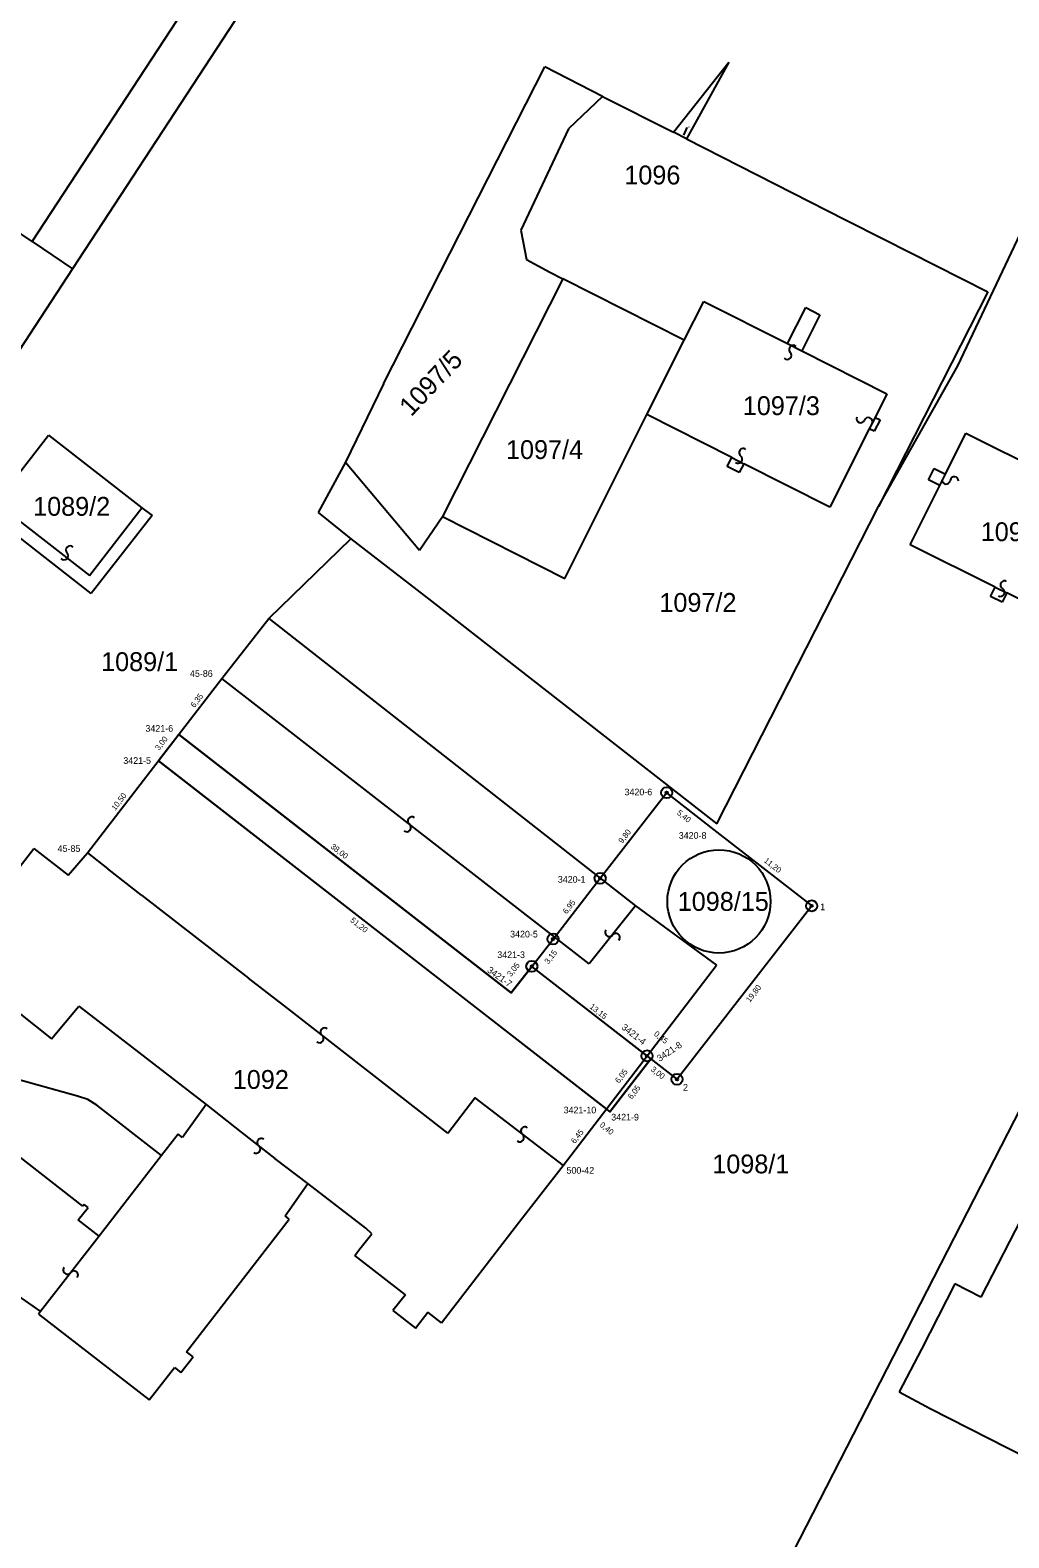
# Model space of a CAD drawing. Extents: x -621172 to -616925, y -1123899 to -1119548.
# Drawn here: x -619154.3 to -619066, y -1121541.1 to -1121405.1 of the extents above; entities that cross this region are included whole.
import ezdxf

# ---------------------------------------------------------------- set-up
doc = ezdxf.new("R2010")
doc.units = 0
for name, color, linetype in [('Vrstva 1', 7, 'Continuous'), ('Vrstva 16', 7, 'Continuous'), ('Vrstva 18', 7, 'Continuous'), ('Vrstva 19', 7, 'Continuous'), ('Vrstva 24', 7, 'Continuous'), ('Vrstva 25', 7, 'Continuous'), ('Vrstva 4', 7, 'Continuous'), ('Vrstva 58', 7, 'Continuous'), ('Vrstva 60', 7, 'Continuous')]:
    doc.layers.add(name, color=color, linetype=linetype)

msp = doc.modelspace()

# ---------------------------------------------------------------- linework, layer by layer
at = {"layer": 'Vrstva 1'}
for points in [[(-619154.13, -1121424.18), (-619231.87, -1121371.5)], [(-619154.13, -1121424.18), (-619131.38, -1121389.44)], [(-619126.66, -1121390.22), (-619150.5, -1121426.64)], [(-619070.6, -1121435.39), (-619056.33, -1121405.28)], [(-619122.41, -1121437.01), (-619107.86, -1121408.43)], [(-619102.66, -1121411.09), (-619107.86, -1121408.43)], [(-619096.26, -1121414.32), (-619091.26, -1121408.01)], [(-619091.26, -1121408.01), (-619095.07, -1121414.92)], [(-619102.66, -1121411.09), (-619105.72, -1121414.02)], [(-619102.66, -1121411.09), (-619096.26, -1121414.32)], [(-619105.72, -1121414.02), (-619110.04, -1121423.16)], [(-619095.07, -1121414.92), (-619096.26, -1121414.32)], [(-619095.07, -1121414.92), (-619080.74, -1121422.22)], [(-619080.74, -1121422.22), (-619077.26, -1121423.98)], [(-619154.13, -1121424.18), (-619150.5, -1121426.64)], [(-619110.04, -1121423.16), (-619109.52, -1121425.79)], [(-619077.26, -1121423.98), (-619067.88, -1121428.73)], [(-619150.5, -1121426.64), (-619163.54, -1121446.57)], [(-619109.52, -1121425.79), (-619107.42, -1121426.94)], [(-619107.42, -1121426.94), (-619106.24, -1121427.54)], [(-619106.24, -1121427.54), (-619117.1, -1121449)], [(-619095.28, -1121433.09), (-619106.24, -1121427.54)], [(-619095.28, -1121433.09), (-619093.5, -1121429.58)], [(-619093.5, -1121429.58), (-619085.97, -1121433.39)], [(-619067.88, -1121428.73), (-619077.75, -1121448.09)], [(-619085.97, -1121433.39), (-619084.32, -1121430.12)], [(-619083.03, -1121430.78), (-619084.68, -1121434.04)], [(-619084.32, -1121430.12), (-619083.03, -1121430.78)], [(-619098.66, -1121439.79), (-619095.28, -1121433.09)], [(-619084.68, -1121434.04), (-619076.99, -1121437.93)], [(-619077.75, -1121448.09), (-619070.6, -1121435.39)], [(-619122.41, -1121437.01), (-619125.86, -1121444.07)], [(-619076.99, -1121437.93), (-619078.06, -1121440.04)], [(-619106.06, -1121454.59), (-619098.66, -1121439.79)], [(-619090.99, -1121443.67), (-619098.66, -1121439.79)], [(-619077.61, -1121440.27), (-619078.13, -1121441.29)], [(-619078.06, -1121440.04), (-619077.61, -1121440.27)], [(-619157.41, -1121447.76), (-619152.66, -1121441.64)], [(-619152.66, -1121441.64), (-619144.22, -1121448.19)], [(-619078.58, -1121441.07), (-619082.15, -1121448.14)], [(-619078.13, -1121441.29), (-619078.58, -1121441.07)], [(-619071.71, -1121445.16), (-619069.87, -1121441.47)], [(-619069.87, -1121441.47), (-619062.56, -1121445.12)], [(-619125.86, -1121444.07), (-619128.32, -1121448.62)], [(-619125.86, -1121444.07), (-619119.18, -1121452.03)], [(-619091.4, -1121444.47), (-619090.99, -1121443.67)], [(-619090.31, -1121445.02), (-619091.4, -1121444.47)], [(-619089.9, -1121444.22), (-619090.31, -1121445.02)], [(-619082.15, -1121448.14), (-619089.9, -1121444.22)], [(-619073.24, -1121445.68), (-619072.73, -1121444.65)], [(-619072.22, -1121446.19), (-619073.24, -1121445.68)], [(-619072.73, -1121444.65), (-619071.71, -1121445.16)], [(-619074.88, -1121451.54), (-619072.22, -1121446.19)], [(-619148.81, -1121455.94), (-619158.11, -1121448.67)], [(-619144.22, -1121448.19), (-619143.3, -1121448.91)], [(-619128.32, -1121448.62), (-619125.37, -1121451)], [(-619092.34, -1121476.71), (-619077.75, -1121448.09)], [(-619143.3, -1121448.91), (-619148.81, -1121455.94)], [(-619119.18, -1121452.03), (-619117.1, -1121449)], [(-619117.1, -1121449), (-619106.06, -1121454.59)], [(-619132.76, -1121458.2), (-619125.37, -1121451)], [(-619125.37, -1121451), (-619118.1, -1121456.61)], [(-619067.21, -1121455.36), (-619074.88, -1121451.54)], [(-619067.63, -1121456.2), (-619067.21, -1121455.36)], [(-619118.1, -1121456.61), (-619092.34, -1121476.71)], [(-619066.58, -1121456.72), (-619067.63, -1121456.2)], [(-619066.16, -1121455.88), (-619066.58, -1121456.72)], [(-619058.52, -1121459.68), (-619066.16, -1121455.88)], [(-619137.02, -1121463.61), (-619132.76, -1121458.2)], [(-619132.76, -1121458.2), (-619102.87, -1121481.62)], [(-619149.15, -1121479.34), (-619137.02, -1121463.61)], [(-619140.9, -1121468.65), (-619110.9, -1121491.96), (-619109.04, -1121489.57)], [(-619102.31, -1121502.43), (-619142.74, -1121471.02)], [(-619102.87, -1121481.62), (-619096.87, -1121473.9)], [(-619096.87, -1121473.9), (-619092.61, -1121477.25)], [(-619092.61, -1121477.25), (-619083.78, -1121484.11)], [(-619161.05, -1121488.05), (-619153.98, -1121478.94)], [(-619153.98, -1121478.94), (-619150.88, -1121481.34)], [(-619150.88, -1121481.34), (-619149.15, -1121479.34)], [(-619107.12, -1121487.1), (-619102.87, -1121481.62)], [(-619102.87, -1121481.62), (-619099.68, -1121484.12)], [(-619099.68, -1121484.12), (-619092.36, -1121489.45)], [(-619083.78, -1121484.11), (-619095.93, -1121499.75)], [(-619109.04, -1121489.57), (-619107.12, -1121487.1)], [(-619161.26, -1121489.06), (-619152.38, -1121496.1)], [(-619098.64, -1121497.64), (-619092.36, -1121489.45)], [(-619098.64, -1121497.64), (-619109.04, -1121489.57)], [(-619152.38, -1121496.1), (-619149.92, -1121493.15)], [(-619149.92, -1121493.15), (-619138.43, -1121502.02)], [(-619150.05, -1121501.29), (-619164.96, -1121497.14)], [(-619106.22, -1121507.53), (-619098.64, -1121497.64)], [(-619095.93, -1121499.75), (-619098.64, -1121497.64)], [(-619098.29, -1121497.91), (-619102, -1121502.68), (-619102.31, -1121502.43)], [(-619149.56, -1121511.19), (-619164.31, -1121499.7)], [(-619149.12, -1121501.57), (-619150.05, -1121501.29)], [(-619148.31, -1121502.09), (-619149.12, -1121501.57)], [(-619142.46, -1121506.63), (-619148.31, -1121502.09)], [(-619138.43, -1121502.02), (-619140.56, -1121505)], [(-619064.91, -1121502.3), (-619094.57, -1121560.13)], [(-619140.96, -1121504.7), (-619142.46, -1121506.63)], [(-619140.56, -1121505), (-619140.96, -1121504.7)], [(-619142.46, -1121506.63), (-619148.1, -1121513.9)], [(-619110.23, -1121512.71), (-619106.22, -1121507.53)], [(-619131.3, -1121512.06), (-619129.25, -1121509.14)], [(-619124.01, -1121513.17), (-619129.25, -1121509.14)], [(-619149.44, -1121511.04), (-619149.56, -1121511.19)], [(-619149.09, -1121511.33), (-619149.44, -1121511.04)], [(-619149.97, -1121512.44), (-619149.09, -1121511.33)], [(-619148.1, -1121513.9), (-619149.97, -1121512.44)], [(-619140.19, -1121524.33), (-619130.94, -1121512.38)], [(-619130.94, -1121512.38), (-619131.3, -1121512.06)], [(-619064.4, -1121511.4), (-619068.52, -1121519.41)], [(-619124.57, -1121515.05), (-619123.47, -1121513.69)], [(-619123.47, -1121513.69), (-619124.01, -1121513.17)], [(-619117.2, -1121521.71), (-619110.23, -1121512.71)], [(-619125, -1121515.66), (-619124.57, -1121515.05)], [(-619120.45, -1121519.19), (-619125, -1121515.66)], [(-619155.46, -1121519.27), (-619153.38, -1121520.7)], [(-619120.45, -1121519.19), (-619121.57, -1121520.6)], [(-619070.85, -1121518.21), (-619073.88, -1121524.1)], [(-619068.52, -1121519.41), (-619070.85, -1121518.21)], [(-619153.38, -1121520.7), (-619153.56, -1121520.93)], [(-619121.57, -1121520.6), (-619119.55, -1121522.19)], [(-619119.55, -1121522.19), (-619118.43, -1121520.76)], [(-619117.2, -1121521.71), (-619118.43, -1121520.76)], [(-619153.56, -1121520.93), (-619143.57, -1121528.68)], [(-619140.7, -1121526.2), (-619139.6, -1121524.79)], [(-619139.6, -1121524.79), (-619140.19, -1121524.33)], [(-619073.88, -1121524.1), (-619075.89, -1121527.96)], [(-619143.57, -1121528.68), (-619141.29, -1121525.74)], [(-619141.29, -1121525.74), (-619140.7, -1121526.2)], [(-619075.89, -1121527.96), (-619073.1, -1121529.44)], [(-619073.1, -1121529.44), (-619062.57, -1121534.81)]]:
    msp.add_lwpolyline(points, dxfattribs=at)
msp.add_lwpolyline([(-619102, -1121502.68), (-619098.29, -1121497.91), (-619109.04, -1121489.57), (-619110.9, -1121491.96), (-619140.9, -1121468.65), (-619142.74, -1121471.02)], close=True, dxfattribs=at)
at = {"layer": 'Vrstva 16'}
msp.add_line((-619095.04, -1121413.9), (-619095.355, -1121414.596), dxfattribs=at)
at = {"layer": 'Vrstva 18'}
msp.add_circle((-619092.15, -1121483.71), 4.656, dxfattribs=at)
at = {"layer": 'Vrstva 24'}
for centre, radius in [((-619096.87, -1121473.9), 0.5), ((-619096.87, -1121473.9), 0.1), ((-619102.87, -1121481.62), 0.5), ((-619102.87, -1121481.62), 0.1), ((-619083.78, -1121484.11), 0.5), ((-619083.78, -1121484.11), 0.1), ((-619107.12, -1121487.1), 0.5), ((-619107.12, -1121487.1), 0.1), ((-619109.04, -1121489.57), 0.5), ((-619109.04, -1121489.57), 0.1), ((-619098.64, -1121497.64), 0.5), ((-619098.64, -1121497.64), 0.1), ((-619095.93, -1121499.75), 0.5), ((-619095.93, -1121499.75), 0.1)]:
    msp.add_circle(centre, radius, dxfattribs=at)
at = {"layer": 'Vrstva 25'}
for centre, start, end in [((-619085.451, -1121433.918), 44.22538, 224.22538), ((-619085.989, -1121434.442), 224.22538, 44.22537), ((-619079.368, -1121440.16), 158.09026, 338.09026), ((-619078.672, -1121440.44), 338.09026, 158.09026), ((-619089.96, -1121443.223), 52.25716, 232.25716), ((-619090.42, -1121443.817), 232.25716, 52.25716), ((-619071.653, -1121445.69), 173.81811, 353.81811), ((-619070.907, -1121445.77), 353.81811, 173.81811), ((-619151.263, -1121452.528), 223.3699, 43.3699), ((-619150.717, -1121452.012), 43.3699, 223.3699), ((-619066.744, -1121455.817), 240.58114, 60.58114), ((-619066.376, -1121455.163), 60.58114, 240.58114), ((-619120.319, -1121477.047), 232.29046, 52.29046), ((-619119.861, -1121476.453), 52.29046, 232.29046), ((-619102.053, -1121486.496), 141.37186, 321.37186), ((-619101.467, -1121486.964), 321.37186, 141.37186), ((-619128.2, -1121496.086), 232.15921, 52.15921), ((-619127.74, -1121495.494), 52.15921, 232.15921), ((-619109.662, -1121504.422), 52.62888, 232.62888), ((-619133.91, -1121506.057), 232.26452, 52.26452), ((-619133.45, -1121505.463), 52.26452, 232.26452), ((-619110.118, -1121505.018), 232.62888, 52.62888), ((-619150.957, -1121516.961), 142.39674, 322.39674), ((-619150.363, -1121517.419), 322.39674, 142.39674)]:
    msp.add_arc(centre, 0.375, start, end, dxfattribs=at)
at = {"layer": 'Vrstva 4'}
for points in [[(-619085.97, -1121433.39), (-619084.68, -1121434.04)], [(-619078.06, -1121440.04), (-619078.58, -1121441.07)], [(-619090.99, -1121443.67), (-619089.9, -1121444.22)], [(-619072.22, -1121446.19), (-619071.71, -1121445.16)], [(-619157.41, -1121447.76), (-619148.96, -1121454.32)], [(-619148.96, -1121454.32), (-619144.22, -1121448.19)], [(-619067.21, -1121455.36), (-619066.16, -1121455.88)], [(-619103.85, -1121489.35), (-619137.02, -1121463.61)], [(-619149.15, -1121479.34), (-619147.3, -1121480.78)], [(-619144.27, -1121483.13), (-619147.3, -1121480.78)], [(-619144.27, -1121483.13), (-619134.61, -1121490.63)], [(-619099.68, -1121484.12), (-619103.85, -1121489.35)], [(-619131.07, -1121493.38), (-619134.61, -1121490.63)], [(-619116.62, -1121504.61), (-619131.07, -1121493.38)], [(-619116.62, -1121504.61), (-619114.18, -1121501.43), (-619106.22, -1121507.53)], [(-619138.43, -1121502.02), (-619135.28, -1121504.52)], [(-619135.28, -1121504.52), (-619132.22, -1121506.89)], [(-619129.25, -1121509.14), (-619132.22, -1121506.89)], [(-619148.1, -1121513.9), (-619153.38, -1121520.7)]]:
    msp.add_lwpolyline(points, dxfattribs=at)

# ---------------------------------------------------------------- texts
at = {"layer": 'Vrstva 16'}
msp.add_text('1096', height=1.7, dxfattribs=at).set_placement((-619100.688, -1121419.03))
at = {"layer": 'Vrstva 18'}
for s, height, p in [('1096', 0.1, (-619095.04, -1121413.9)), ('1097/2', 1.7, (-619097.523, -1121457.59)), ('1089/1', 1.7, (-619147.91, -1121462.93)), ('1098/15', 1.7, (-619095.87, -1121484.56)), ('1098/1', 1.7, (-619092.75, -1121508.24))]:
    msp.add_text(s, height=height, dxfattribs=at).set_placement(p)
msp.add_text('1097/5', height=1.7, rotation=46.8, dxfattribs=at).set_placement((-619119.92, -1121440.041))
at = {"layer": 'Vrstva 19'}
for s, p in [('1097/3', (-619089.995, -1121439.84)), ('1097/4', (-619111.368, -1121443.8)), ('1089/2', (-619154.043, -1121448.92)), ('1098/10', (-619068.522, -1121451.21)), ('1092', (-619136.024, -1121500.62))]:
    msp.add_text(s, height=1.7, dxfattribs=at).set_placement(p)
at = {"layer": 'Vrstva 58'}
for s, rotation, p in [('6,35', 52.40944, (-619139.479, -1121466.28)), ('3,00', 52.17526, (-619142.685, -1121470.134)), ('10,50', 52.38817, (-619146.636, -1121475.553)), ('5,40', 321.81902, (-619095.996, -1121475.808)), ('9,80', 52.14558, (-619100.868, -1121478.522)), ('38,00', 322.15279, (-619127.248, -1121478.853)), ('11,20', 322.15648, (-619088.138, -1121480.116)), ('6,95', 52.20473, (-619105.887, -1121484.89)), ('51,20', 322.15643, (-619125.466, -1121485.504)), ('3,15', 52.14108, (-619107.541, -1121489.402)), ('3,05', 52.10842, (-619110.915, -1121490.546)), ('19,80', 52.158, (-619089.359, -1121492.857)), ('13,15', 322.18991, (-619103.87, -1121493.303)), ('0,45', 322.35238, (-619098.065, -1121495.76)), ('6,05', 52.5414, (-619101.169, -1121500.152)), ('3,00', 322.05785, (-619098.35, -1121498.953)), ('6,05', 52.12502, (-619100.017, -1121501.597)), ('6,45', 52.52382, (-619105.145, -1121505.602)), ('0,40', 321.1155, (-619102.961, -1121503.96))]:
    msp.add_text(s, height=0.52, rotation=rotation, dxfattribs=at).set_placement(p)
at = {"layer": 'Vrstva 60'}
for s, p in [('45-86', (-619139.89, -1121463.45)), ('3421-6', (-619143.909, -1121468.4)), ('3421-5', (-619145.906, -1121471.3)), ('3420-6', (-619100.67, -1121474.14)), ('45-85', (-619151.837, -1121479.24)), ('3420-8', (-619095.777, -1121478.06)), ('3420-1', (-619106.691, -1121482.02)), ('1', (-619083.01, -1121484.5)), ('3420-5', (-619110.997, -1121486.96)), ('3421-3', (-619112.156, -1121488.82)), ('2', (-619095.39, -1121500.78)), ('3421-10', (-619106.167, -1121502.83)), ('3421-9', (-619101.87, -1121503.47)), ('500-42', (-619105.91, -1121508.27))]:
    msp.add_text(s, height=0.6, dxfattribs=at).set_placement(p)
for s, rotation, p in [('3421-7', 324.42701, (-619113.125, -1121490.031)), ('3421-4', 322.08151, (-619101.001, -1121495.17)), ('3421-8', 33.61206, (-619097.504, -1121498.19))]:
    msp.add_text(s, height=0.6, rotation=rotation, dxfattribs=at).set_placement(p)

doc.saveas('drawing.dxf')
